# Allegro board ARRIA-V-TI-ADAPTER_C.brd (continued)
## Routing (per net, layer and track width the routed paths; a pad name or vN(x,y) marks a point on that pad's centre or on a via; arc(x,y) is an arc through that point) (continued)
DA2N: length 162.7
  TOP w0.114: J2.153 222.25,36.96 222.17,37.04 214.13,37.04 214,36.92 214,17.91 213.7,17.6 124.84,17.6 124.55,17.89 124.55,21.06 124.42,21.18 124.1,21.18 123.98,21.06 123.98,17.89 123.69,17.6 122.68,17.6 122.38,17.91 122.38,22.63 122.26,22.75 121.92,22.75 121.8,22.63 121.8,19.69 121.5,19.38 120.93,19.38 120.62,19.69 120.62,22.63 120.51,22.75 120.17,22.75 120.05,22.63 120.05,19.69 119.75,19.38 119.18,19.38 118.87,19.69 118.87,22.43 118.53,22.77 105.93,22.77 v1(105.42,22.26)
  BOTTOM w0.114: v1(105.42,22.26) J3.H10
DA2P: length 162.7
  TOP w0.114: v1(105.42,23.53) 105.88,23.08 118.66,23.08 119.18,22.56 119.18,19.81 119.3,19.68 119.62,19.68 119.75,19.81 119.75,22.76 120.04,23.05 120.64,23.05 120.93,22.76 120.93,19.81 121.05,19.68 121.37,19.68 121.5,19.81 121.5,22.76 121.79,23.05 122.39,23.05 122.68,22.76 122.68,18.03 122.81,17.91 123.56,17.91 123.67,18.02 123.67,21.18 123.98,21.49 124.55,21.49 124.85,21.18 124.85,18.02 124.97,17.91 213.57,17.91 213.7,18.03 213.7,37.04 214.01,37.35 222.14,37.35 222.25,37.46 J2.151
  BOTTOM w0.114: v1(105.42,23.53) J3.H11
DA3N: length 161.2
  TOP w0.114: v1(99.07,27.34) 99.11,27.38 99.11,27.71 99.24,27.84 99.44,27.84 99.57,27.71 99.57,25.58 99.85,25.3 103.15,25.3 103.38,25.06 103.38,24.48 103.39,24.48 103.39,24.32 103.71,24 126.11,24 126.24,23.88 126.24,20.04 126.54,19.74 127.46,19.74 127.76,20.04 127.76,23.88 127.89,24 128.4,24 128.52,23.88 128.52,19.43 128.83,19.13 211.53,19.13 211.84,19.43 211.84,38.43 211.96,38.56 222.4,38.56 222.49,38.46 J2.147
  BOTTOM w0.114: v1(99.07,27.34) J3.C14
DA3P: length 161.2
  TOP w0.114: v1(99.07,28.61) 99.09,28.6 99.09,28.24 99.19,28.14 99.57,28.14 99.87,27.84 99.87,25.7 99.97,25.6 103.28,25.6 103.69,25.19 103.69,24.61 103.7,24.6 103.7,24.45 103.83,24.31 126.24,24.31 126.54,24 126.54,20.17 126.67,20.04 127.33,20.04 127.46,20.17 127.46,24 127.76,24.31 128.52,24.31 128.83,24 128.83,19.56 128.96,19.43 211.4,19.43 211.53,19.56 211.53,38.56 211.84,38.87 222.4,38.87 222.49,38.96 J2.145
  BOTTOM w0.114: v1(99.07,28.61) J3.C15
DA4N: length 162.1
  TOP w0.114: J2.141 222.49,39.96 222.4,40.06 210.18,40.06 209.99,39.88 209.99,21.4 209.37,20.78 138.16,20.78 137.87,21.07 137.87,21.54 137.74,21.67 137.42,21.67 137.29,21.54 137.29,21.07 137,20.78 135.86,20.78 135.57,21.07 135.57,25.15 135.44,25.27 134.67,25.27 134.54,25.15 134.54,21.08 134.24,20.78 133.27,20.78 132.97,21.08 132.97,25.15 132.84,25.27 132,25.27 131.88,25.15 131.88,21.21 131.57,20.9 130.73,20.9 130.43,21.21 130.43,25.16 130.3,25.29 104.28,25.29 104.15,25.16 v1(104.15,24.8)
  BOTTOM w0.114: v1(104.15,24.8) J3.G12
DA4P: length 162.1
  TOP w0.114: v1(104.15,26.07) 104.15,25.72 104.28,25.59 130.43,25.59 130.73,25.29 130.73,21.34 130.86,21.21 131.44,21.21 131.57,21.34 131.57,25.27 131.88,25.58 132.97,25.58 133.27,25.27 133.27,21.21 133.4,21.08 134.11,21.08 134.24,21.21 134.24,25.27 134.54,25.58 135.57,25.58 135.88,25.27 135.88,21.2 135.99,21.08 136.87,21.08 136.99,21.2 136.99,21.67 137.29,21.97 137.86,21.97 138.17,21.67 138.17,21.2 138.28,21.08 209.25,21.08 209.69,21.53 209.69,40.01 210.05,40.37 222.4,40.37 222.49,40.46 J2.139
  BOTTOM w0.114: v1(104.15,26.07) J3.G13
DA5N: length 160.7
  TOP w0.114: J2.135 222.49,41.47 222.4,41.56 208.82,41.56 208.53,41.28 208.53,22.61 208.23,22.3 142.32,22.3 142.03,22.59 142.03,26.33 141.9,26.45 141.4,26.45 141.27,26.33 141.27,23.51 140.97,23.2 140.26,23.2 139.95,23.51 139.95,26.29 139.83,26.42 138.99,26.42 138.86,26.29 138.86,23.5 138.56,23.19 137.47,23.19 137.16,23.5 137.16,26.43 137.03,26.56 102.41,26.56 102.11,26.86 102.11,27.66 101.94,27.83 100.47,27.83 100.34,27.7 v1(100.34,27.34)
  BOTTOM w0.114: v1(100.34,27.34) J3.D14
DA5P: length 160.7
  TOP w0.114: J2.133 222.49,41.97 222.4,41.87 208.7,41.87 208.23,41.4 208.23,22.73 208.1,22.61 142.45,22.61 142.33,22.72 142.33,26.45 142.03,26.76 141.28,26.76 140.97,26.45 140.97,23.63 140.84,23.51 140.39,23.51 140.26,23.63 140.26,26.42 139.95,26.72 138.86,26.72 138.56,26.42 138.56,23.62 138.43,23.5 137.59,23.5 137.46,23.62 137.46,26.56 137.16,26.86 102.54,26.86 102.41,26.99 102.41,27.79 102.07,28.13 100.47,28.13 100.34,28.26 v1(100.34,28.61)
  BOTTOM w0.114: v1(100.34,28.61) J3.D15
DA6N: length 162.5
  TOP w0.114: v1(104.15,28.61) 104.63,29.1 105.63,29.1 105.89,28.83 105.89,28.13 106.2,27.83 144.14,27.83 144.27,27.7 144.27,24.64 144.58,24.33 145.41,24.33 145.72,24.64 145.72,27.7 145.85,27.83 146.43,27.83 146.56,27.7 146.56,24.64 146.86,24.33 147.7,24.33 148.01,24.64 148.01,27.69 148.13,27.81 148.71,27.81 148.84,27.69 148.84,24.64 149.15,24.33 149.94,24.33 150.24,24.64 150.24,27.58 150.37,27.71 150.83,27.71 150.95,27.58 150.95,24.64 151.26,24.33 205.99,24.33 206.3,24.64 206.3,42.67 206.69,43.06 222.4,43.06 222.49,42.97 J2.129
  BOTTOM w0.114: v1(104.15,28.61) J3.G15
DA6P: length 162.5
  TOP w0.114: v1(104.15,29.88) 104.63,29.4 105.75,29.4 106.2,28.96 106.2,28.26 106.32,28.13 144.27,28.13 144.58,27.83 144.58,24.77 144.7,24.64 145.29,24.64 145.41,24.77 145.41,27.83 145.72,28.13 146.56,28.13 146.86,27.83 146.86,24.77 146.99,24.64 147.57,24.64 147.7,24.77 147.7,27.81 148.01,28.12 148.84,28.12 149.15,27.81 149.15,24.77 149.27,24.64 149.81,24.64 149.94,24.77 149.94,27.71 150.24,28.02 150.95,28.02 151.26,27.71 151.26,24.77 151.38,24.64 205.87,24.64 205.99,24.77 205.99,42.8 206.56,43.37 222.4,43.37 222.49,43.47 J2.127
  BOTTOM w0.114: v1(104.15,29.88) J3.G16
DA7N: length 129.9
  TOP w0.114: v1(106.69,28.61) 107.17,29.1 198.08,29.1 203.96,34.98 203.96,43.89 204.64,44.57 222.4,44.57 222.49,44.47 J2.123
  BOTTOM w0.114: v1(106.69,28.61) J3.J15
DA7P: length 129.9
  TOP w0.114: v1(106.69,29.88) 107.17,29.4 197.96,29.4 203.66,35.1 203.66,44.02 204.51,44.87 222.4,44.87 222.49,44.97 J2.121
  BOTTOM w0.114: v1(106.69,29.88) J3.J16
DA8N: length 161.3
  TOP w0.114: J2.111 222.49,52.46 222.4,52.56 219.46,52.56 219.33,52.43 219.33,47.37 219.02,47.07 218.25,47.07 217.94,47.37 217.94,52.44 217.83,52.56 217.49,52.56 217.37,52.44 217.37,47.37 217.07,47.07 216.33,47.07 216.03,47.37 216.03,49.24 215.9,49.37 215.44,49.37 215.32,49.24 215.32,46.91 215.01,46.61 197.23,46.61 196.72,46.1 196.72,31.37 195.72,30.37 102.41,30.37 102.11,30.67 102.11,31.47 101.94,31.64 100.82,31.64 v1(100.34,31.15)
  BOTTOM w0.114: v1(100.34,31.15) J3.D17
DA8P: length 161.3
  TOP w0.114: J2.109 222.49,52.96 222.4,52.86 219.33,52.86 219.02,52.56 219.02,47.5 218.9,47.37 218.38,47.37 218.25,47.5 218.25,52.57 217.96,52.86 217.36,52.86 217.07,52.57 217.07,47.5 216.94,47.37 216.46,47.37 216.33,47.5 216.33,49.37 216.03,49.68 215.32,49.68 215.01,49.37 215.01,47.04 214.88,46.91 197.1,46.91 196.42,46.23 196.42,31.5 195.59,30.67 102.54,30.67 102.41,30.8 102.41,31.6 102.07,31.94 100.82,31.94 v1(100.34,32.42)
  BOTTOM w0.114: v1(100.34,32.42) J3.D18
DA9N: length 160.9
  TOP w0.114: v1(104.15,32.42) 104.63,32.91 105.75,32.91 105.92,32.74 105.92,31.94 106.22,31.64 192.67,31.64 193.55,32.51 193.55,47.57 194.49,48.51 208.03,48.51 208.41,48.9 208.41,50.29 208.53,50.42 209.25,50.42 209.37,50.29 209.37,48.82 209.68,48.51 210.51,48.51 210.82,48.82 210.82,53.93 210.95,54.06 211.4,54.06 211.53,53.93 211.53,48.82 211.84,48.51 212.8,48.51 213.11,48.82 213.11,53.93 213.23,54.06 213.69,54.06 213.82,53.93 213.82,52.03 214.12,51.73 215.21,51.73 215.52,52.03 215.52,53.93 215.65,54.06 222.4,54.06 222.49,53.96 J2.105
  BOTTOM w0.114: v1(104.15,32.42) J3.G18
DA9P: length 160.9
  TOP w0.114: J2.103 222.49,54.46 222.4,54.36 215.52,54.36 215.21,54.06 215.21,52.16 215.09,52.03 214.25,52.03 214.12,52.16 214.12,54.06 213.82,54.36 213.11,54.36 212.8,54.06 212.8,48.95 212.67,48.82 211.96,48.82 211.84,48.95 211.84,54.06 211.53,54.36 210.82,54.36 210.52,54.06 210.52,48.95 210.39,48.82 209.8,48.82 209.68,48.95 209.68,50.42 209.37,50.72 208.41,50.72 208.1,50.42 208.1,49.02 207.9,48.82 194.36,48.82 193.24,47.7 193.24,32.64 192.55,31.94 106.35,31.94 106.22,32.07 106.22,32.87 105.88,33.21 104.63,33.21 v1(104.15,33.69)
  BOTTOM w0.114: v1(104.15,33.69) J3.G19
DA10N: length 160.9
  TOP w0.114: J2.99 222.49,55.46 222.4,55.56 209.36,55.56 209.3,55.5 209.3,52.71 208.99,52.4 208.23,52.4 207.92,52.71 207.92,55.37 207.79,55.5 206.76,55.5 206.63,55.37 206.63,51.05 206.32,50.75 205.16,50.75 204.85,51.05 204.85,55.43 204.72,55.56 204.09,55.56 203.96,55.43 203.96,51.05 203.66,50.75 202.44,50.75 202.13,51.05 202.13,54.1 202.01,54.23 201.29,54.23 201.17,54.1 201.17,51.31 200.53,50.67 191.26,50.67 190.88,50.29 190.88,34.04 189.75,32.91 107.17,32.91 v1(106.69,32.42)
  BOTTOM w0.114: v1(106.69,32.42) J3.J18
DA10P: length 160.9
  TOP w0.114: v1(106.69,33.69) 107.17,33.21 189.62,33.21 190.58,34.16 190.58,50.42 191.13,50.98 200.41,50.98 200.86,51.43 200.86,54.23 201.17,54.53 202.13,54.53 202.44,54.23 202.44,51.18 202.56,51.05 203.53,51.05 203.66,51.18 203.66,55.56 203.96,55.87 204.85,55.87 205.16,55.56 205.16,51.18 205.28,51.05 206.2,51.05 206.32,51.18 206.32,55.5 206.63,55.8 207.92,55.8 208.23,55.5 208.23,52.83 208.35,52.7 208.86,52.7 208.99,52.83 208.99,55.63 209.23,55.87 222.4,55.87 222.49,55.96 J2.97
  BOTTOM w0.114: v1(106.69,33.69) J3.J19
DA11N: length 155.8
  TOP w0.114: J2.93 222.49,56.96 222.4,57.06 199.52,57.06 199.39,56.94 199.39,52.71 199.08,52.4 198.25,52.4 197.94,52.71 197.94,56.9 197.82,57.02 197.23,57.02 197.1,56.9 197.1,52.71 196.8,52.4 195.97,52.4 195.66,52.71 195.66,56.72 195.54,56.85 194.87,56.85 194.74,56.72 194.74,52.63 194.44,52.32 188.14,52.32 187.71,51.89 187.71,35.31 186.58,34.18 108.44,34.18 v1(107.96,33.69)
  BOTTOM w0.114: v1(107.96,33.69) J3.K19
DA11P: length 155.8
  TOP w0.114: J2.91 222.49,57.46 222.4,57.37 199.39,57.37 199.09,57.06 199.09,52.83 198.96,52.7 198.37,52.7 198.25,52.83 198.25,57.02 197.94,57.33 197.1,57.33 196.8,57.02 196.8,52.83 196.67,52.7 196.09,52.7 195.97,52.83 195.97,56.84 195.66,57.15 194.74,57.15 194.44,56.84 194.44,52.76 194.31,52.63 188.01,52.63 187.4,52.02 187.4,35.43 186.45,34.48 108.44,34.48 v1(107.96,34.96)
  BOTTOM w0.114: v1(107.96,34.96) J3.K20
DA12N: length 160.8
  TOP w0.114: v1(101.61,32.42) 102.09,32.91 103.19,32.91 103.68,33.4 103.68,35.18 103.93,35.43 183.89,35.43 184.91,36.45 184.91,53.8 185.04,53.92 188.09,53.92 188.39,54.23 188.39,58.42 188.52,58.55 189.1,58.55 189.23,58.42 189.23,55.13 189.54,54.83 190.25,54.83 190.55,55.13 190.55,58.42 190.68,58.55 191.21,58.55 191.34,58.42 191.34,55.5 191.64,55.19 192.61,55.19 192.91,55.5 192.91,58.44 193.04,58.56 222.4,58.56 222.49,58.47 J2.87
  BOTTOM w0.114: v1(101.61,32.42) J3.E18
DA12P: length 160.8
  TOP w0.114: J2.85 222.49,58.97 222.4,58.87 192.91,58.87 192.61,58.56 192.61,55.63 192.48,55.5 191.77,55.5 191.64,55.63 191.64,58.55 191.34,58.85 190.55,58.85 190.25,58.55 190.25,55.26 190.12,55.13 189.66,55.13 189.53,55.26 189.53,58.55 189.23,58.85 188.39,58.85 188.09,58.55 188.09,54.36 187.96,54.23 184.91,54.23 184.61,53.92 184.61,36.58 183.76,35.73 103.8,35.73 103.38,35.31 103.38,33.53 103.06,33.21 102.09,33.21 v1(101.61,33.69)
  BOTTOM w0.114: v1(101.61,33.69) J3.E19
DA13N: length 159.4
  TOP w0.114: J2.81 222.49,59.97 222.4,60.06 179.84,60.06 179.72,59.94 179.72,59.05 179.84,58.93 185.04,58.93 185.34,58.62 185.34,57.4 185.04,57.1 182.17,57.1 182.04,56.97 182.04,37.04 181.74,36.74 102.6,36.74 102.42,36.55 102.42,35.9 101.97,35.45 100.82,35.45 v1(100.34,34.96)
  BOTTOM w0.114: v1(100.34,34.96) J3.D20
DA13P: length 159.4
  TOP w0.114: J2.79 222.49,60.47 222.4,60.37 179.72,60.37 179.41,60.06 179.41,58.93 179.72,58.62 184.91,58.62 185.04,58.5 185.04,57.53 184.91,57.4 182.04,57.4 181.74,57.1 181.74,37.17 181.61,37.04 102.48,37.04 102.11,36.68 102.11,36.02 101.84,35.75 100.82,35.75 v1(100.34,36.23)
  BOTTOM w0.114: v1(100.34,36.23) J3.D21
DA14N: length 161
  TOP w0.114: v1(105.42,37.5) 105.9,37.99 174.51,37.99 175.51,38.99 175.51,50.35 175.63,50.47 178.54,50.47 178.84,50.77 178.84,51.34 178.54,51.65 175.63,51.65 175.51,51.76 175.51,52.11 175.63,52.22 178.54,52.22 178.84,52.53 178.84,53.1 178.54,53.4 175.63,53.4 175.51,53.52 175.51,53.86 175.63,53.97 178.55,53.97 178.85,54.28 178.85,54.85 178.55,55.15 175.63,55.15 175.51,55.27 175.51,61.44 175.64,61.57 222.4,61.57 222.49,61.47 J2.75
  BOTTOM w0.114: v1(105.42,37.5) J3.H22
DA14P: length 161
  TOP w0.114: J2.73 222.49,61.97 222.4,61.87 175.51,61.87 175.21,61.57 175.21,55.14 175.5,54.85 178.42,54.85 178.55,54.72 178.55,54.41 178.42,54.28 175.5,54.28 175.21,53.99 175.21,53.39 175.5,53.1 178.41,53.1 178.54,52.97 178.54,52.65 178.41,52.53 175.5,52.53 175.21,52.23 175.21,51.64 175.5,51.34 178.41,51.34 178.54,51.22 178.54,50.9 178.41,50.77 175.5,50.77 175.21,50.48 175.21,39.12 174.38,38.29 105.9,38.29 v1(105.42,38.77)
  BOTTOM w0.114: v1(105.42,38.77) J3.H23
DA15N: length 158.6
  TOP w0.114: v1(99.07,37.5) 99.56,37.99 104.53,37.99 104.92,38.37 104.92,39.14 105.05,39.27 172.47,39.27 172.97,39.78 172.97,62.94 173.1,63.07 207.27,63.07 207.56,63.36 207.56,65.27 207.69,65.39 208.01,65.39 208.14,65.27 208.14,63.36 208.43,63.07 209.02,63.07 209.32,63.36 209.32,65.27 209.44,65.39 209.76,65.39 209.89,65.27 209.89,63.36 210.18,63.07 222.4,63.07 222.49,62.97 J2.69
  BOTTOM w0.114: v1(99.07,37.5) J3.C22
DA15P: length 158.6
  TOP w0.114: J2.67 222.49,63.47 222.4,63.37 210.31,63.37 210.19,63.49 210.19,65.39 209.89,65.7 209.32,65.7 209.01,65.39 209.01,63.49 208.9,63.37 208.55,63.37 208.44,63.49 208.44,65.39 208.14,65.7 207.56,65.7 207.26,65.39 207.26,63.49 207.15,63.37 172.97,63.37 172.67,63.07 172.67,39.9 172.34,39.57 104.92,39.57 104.62,39.27 104.62,38.5 104.41,38.29 99.56,38.29 v1(99.07,38.77)
  BOTTOM w0.114: v1(99.07,38.77) J3.C23
DAC_RST: length 198
  LAYER3 w0.124: v1(210.69,73.66) 210.69,76.58 176.05,111.23 61.82,111.23 52.07,101.47 52.07,92.33 v1(50.91,91.17)
  BOTTOM w0.165: v1(210.69,73.66) R5.1 ; J4.139 v1(50.91,91.17)
DATACLKN: length 141.8
  TOP w0.114: J2.115 222.49,51.46 222.4,51.36 221.47,51.36 v1(221.17,51.66)
  BOTTOM w0.114: J3.J10 106.69,22.26 107.71,22.26 108.28,21.69 170.82,21.69 170.94,21.81 170.94,24.13 171.24,24.43 171.81,24.43 172.12,24.13 172.12,21.81 172.23,21.69 172.58,21.69 172.69,21.81 172.69,24.61 173,24.92 173.57,24.92 173.87,24.61 173.87,21.81 173.99,21.69 174.57,21.69 202.84,49.96 218.31,49.96 219.79,51.44 220.94,51.44 v1(221.17,51.66)
DATACLKP: length 141.8
  TOP w0.114: J2.117 222.49,50.96 222.4,51.06 221.47,51.06 v1(221.17,50.76)
  BOTTOM w0.114: J3.J9 106.69,20.99 107.79,20.99 108.18,21.39 170.95,21.39 171.24,21.68 171.24,24 171.37,24.13 171.69,24.13 171.81,24 171.81,21.68 172.11,21.39 172.7,21.39 172.99,21.68 172.99,24.49 173.12,24.61 173.44,24.61 173.57,24.49 173.57,21.68 173.86,21.39 174.7,21.39 202.97,49.66 218.44,49.66 219.91,51.13 220.8,51.13 v1(221.17,50.76)
DB0N: length 157.5
  TOP w0.114: v1(232.16,33.76) 231.86,34.06 230.99,34.06 230.9,33.96 J2.166
  LAYER3 w0.112: v1(102.88,18.45) 103.36,18.94 210.31,18.94 210.62,19.24 210.62,23.56 210.74,23.69 211.44,23.69 211.57,23.56 211.57,19.23 211.86,18.94 213.11,18.94 213.41,19.24 213.41,33.91 213.56,34.06 225.58,34.06 225.98,33.66 227.2,33.66 227.61,34.06 231.86,34.06 v1(232.16,33.76)
  BOTTOM w0.114: v1(102.88,18.45) J3.F7
DB0P: length 157.5
  TOP w0.114: J2.164 230.9,34.46 230.99,34.36 231.86,34.36 v1(232.16,34.66)
  LAYER3 w0.112: v1(102.88,19.72) 103.36,19.24 210.19,19.24 210.31,19.37 210.31,23.68 210.62,23.99 211.57,23.99 211.87,23.68 211.87,19.35 211.98,19.24 212.98,19.24 213.11,19.37 213.11,34.04 213.43,34.36 225.71,34.36 226.11,33.96 227.08,33.96 227.48,34.36 231.86,34.36 v1(232.16,34.66)
  BOTTOM w0.114: v1(102.88,19.72) J3.F8
DB1N: length 158.6
  TOP w0.114: v1(227.5,35.26) 227.8,35.56 228.13,35.56 228.22,35.46 J2.160
  LAYER3 w0.112: v1(227.5,35.26) 227.2,35.56 208.46,35.56 208.33,35.43 208.33,21.78 208.03,21.48 206.78,21.48 206.49,21.77 206.49,29.3 206.36,29.43 205.41,29.43 205.28,29.3 205.28,21.78 204.98,21.48 102.09,21.48 v1(101.61,20.99)
  BOTTOM w0.114: v1(101.61,20.99) J3.E9
DB1P: length 158.6
  TOP w0.114: v1(227.5,36.16) 227.8,35.86 228.13,35.86 228.22,35.96 J2.158
  LAYER3 w0.112: v1(101.61,22.26) 102.09,21.78 204.85,21.78 204.98,21.91 204.98,29.43 205.28,29.73 206.49,29.73 206.8,29.43 206.8,21.89 206.91,21.78 207.9,21.78 208.03,21.91 208.03,35.56 208.33,35.86 227.2,35.86 v1(227.5,36.16)
  BOTTOM w0.114: v1(101.61,22.26) J3.E10
DB2N: length 160.5
  TOP w0.114: v1(232.16,36.76) 231.86,37.06 230.99,37.06 230.9,36.96 J2.154
  LAYER3 w0.112: v1(101.61,24.8) 102.09,25.29 104.5,25.29 104.62,25.16 104.62,24.33 104.95,24 200.28,24 200.66,24.38 200.66,30.24 200.79,30.37 201.5,30.37 201.63,30.24 201.63,24.38 201.93,24.08 203.07,24.08 203.38,24.38 203.38,36.7 203.73,37.06 225.93,37.06 226.24,37.36 227.28,37.36 227.58,37.06 231.86,37.06 v1(232.16,36.76)
  BOTTOM w0.114: v1(101.61,24.8) J3.E12
DB2P: length 160.5
  TOP w0.114: v1(232.16,37.66) 231.86,37.36 230.99,37.36 230.9,37.46 J2.152
  LAYER3 w0.112: v1(232.16,37.66) 231.86,37.36 227.71,37.36 227.41,37.67 226.11,37.67 225.81,37.36 203.61,37.36 203.07,36.83 203.07,24.51 202.95,24.38 202.06,24.38 201.93,24.51 201.93,30.37 201.62,30.67 200.66,30.67 200.36,30.37 200.36,24.51 200.15,24.31 105.08,24.31 104.93,24.46 104.93,25.29 104.62,25.59 102.09,25.59 v1(101.61,26.07)
  BOTTOM w0.114: v1(101.61,26.07) J3.E13
DB3N: length 153.9
  TOP w0.114: v1(227.5,38.26) 227.8,38.56 228.13,38.56 228.22,38.46 J2.148
  LAYER3 w0.112: v1(227.5,38.26) 227.2,38.56 199.01,38.56 198.68,38.23 198.68,25.65 198.37,25.35 197.03,25.35 196.72,25.65 196.72,33.86 196.6,33.99 195.63,33.99 195.5,33.86 195.5,25.59 195.2,25.29 107.17,25.29 v1(106.69,24.8)
  BOTTOM w0.114: v1(106.69,24.8) J3.J12
DB3P: length 153.9
  TOP w0.114: v1(227.5,39.17) 227.8,38.87 228.13,38.87 228.22,38.96 J2.146
  LAYER3 w0.112: v1(227.5,39.17) 227.2,38.87 198.89,38.87 198.37,38.35 198.37,25.78 198.25,25.65 197.15,25.65 197.03,25.78 197.03,33.98 196.72,34.29 195.5,34.29 195.2,33.98 195.2,25.72 195.07,25.59 107.17,25.59 v1(106.69,26.07)
  BOTTOM w0.114: v1(106.69,26.07) J3.J13
DB4N: length 161.2
  TOP w0.114: v1(232.16,39.76) 231.86,40.06 230.99,40.06 230.9,39.96 J2.142
  LAYER3 w0.112: v1(232.16,39.76) 231.86,40.06 192.89,40.06 192.71,39.88 192.71,26.92 192.4,26.62 191.01,26.62 190.7,26.92 190.7,34.1 190.58,34.23 189.84,34.23 189.72,34.1 189.72,26.85 189.43,26.56 103.36,26.56 v1(102.88,26.07)
  BOTTOM w0.114: v1(102.88,26.07) J3.F13
DB4P: length 161.2
  TOP w0.114: J2.140 230.9,40.46 230.99,40.37 231.86,40.37 v1(232.16,40.67)
  LAYER3 w0.112: v1(232.16,40.67) 231.86,40.37 192.77,40.37 192.41,40.01 192.41,27.05 192.28,26.92 191.13,26.92 191.01,27.05 191.01,34.23 190.7,34.53 189.72,34.53 189.41,34.23 189.41,26.97 189.3,26.86 103.36,26.86 v1(102.88,27.34)
  BOTTOM w0.114: v1(102.88,27.34) J3.F14
DB5N: length 158.5
  TOP w0.114: v1(227.5,41.26) 227.8,41.56 228.13,41.56 228.22,41.47 J2.136
  LAYER3 w0.112: v1(227.5,41.26) 227.2,41.56 186.9,41.56 186.74,41.4 186.74,29.34 186.44,29.03 184.66,29.03 184.35,29.34 184.35,37.64 184.23,37.77 183.29,37.77 183.16,37.64 183.16,29.39 182.87,29.1 102.09,29.1 v1(101.61,28.61)
  BOTTOM w0.114: v1(101.61,28.61) J3.E15
DB5P: length 158.5
  TOP w0.114: J2.134 228.22,41.97 228.13,41.87 227.8,41.87 v1(227.5,42.17)
  LAYER3 w0.112: v1(227.5,42.17) 227.2,41.87 186.77,41.87 186.44,41.53 186.44,29.46 186.31,29.34 184.78,29.34 184.66,29.46 184.66,37.77 184.35,38.07 183.17,38.07 182.86,37.77 182.86,29.51 182.75,29.4 102.09,29.4 v1(101.61,29.88)
  BOTTOM w0.114: v1(101.61,29.88) J3.E16
DB6N: length 161
  TOP w0.114: v1(232.16,42.76) 231.86,43.06 230.99,43.06 230.9,42.97 J2.130
  LAYER3 w0.112: v1(232.16,42.76) 231.86,43.06 180.53,43.06 180.39,42.93 180.39,30.73 180.09,30.43 178.94,30.43 178.64,30.73 178.64,38.2 178.51,38.33 177.34,38.33 177.22,38.2 177.22,30.67 176.91,30.37 103.36,30.37 v1(102.88,29.88)
  BOTTOM w0.114: v1(102.88,29.88) J3.F16
DB6P: length 161
  TOP w0.114: J2.128 230.9,43.47 230.99,43.37 231.86,43.37 v1(232.16,43.67)
  LAYER3 w0.112: v1(102.88,31.15) 103.36,30.67 176.78,30.67 176.91,30.8 176.91,38.33 177.22,38.63 178.64,38.63 178.94,38.33 178.94,30.86 179.07,30.73 179.96,30.73 180.09,30.86 180.09,43.05 180.4,43.37 231.86,43.37 v1(232.16,43.67)
  BOTTOM w0.114: v1(102.88,31.15) J3.F17
DB7N: length 160.9
  TOP w0.114: v1(227.5,44.27) 227.8,44.57 228.13,44.57 228.22,44.47 J2.124
  LAYER3 w0.112: v1(227.5,44.27) 227.2,44.57 175.04,44.57 174.92,44.45 174.92,36.96 174.62,36.65 173.66,36.65 173.35,36.96 173.35,44.58 173.23,44.7 172.26,44.7 172.14,44.58 172.14,37.02 171.83,36.72 170.45,36.72 170.16,37.01 170.16,43.54 170.03,43.66 169.34,43.66 169.21,43.54 169.21,37.02 168.91,36.72 107.17,36.72 v1(106.69,36.23)
  BOTTOM w0.114: v1(106.69,36.23) J3.J21
DB7P: length 160.9
  TOP w0.114: v1(227.5,45.17) 227.8,44.87 228.13,44.87 228.22,44.97 J2.122
  LAYER3 w0.112: v1(227.5,45.17) 227.2,44.87 174.91,44.87 174.62,44.58 174.62,37.08 174.49,36.96 173.79,36.96 173.66,37.08 173.66,44.7 173.35,45.01 172.14,45.01 171.83,44.7 171.83,37.15 171.7,37.02 170.57,37.02 170.46,37.13 170.46,43.66 170.16,43.97 169.22,43.97 168.91,43.66 168.91,37.15 168.78,37.02 107.17,37.02 v1(106.69,37.5)
  BOTTOM w0.114: v1(106.69,37.5) J3.J22
DB8N: length 154.8
  TOP w0.114: J2.112 230.9,52.46 230.99,52.56 231.86,52.56 v1(232.16,52.26)
  LAYER3 w0.112: v1(107.96,37.5) 108.44,37.99 165.61,37.99 165.91,38.29 165.91,51.82 166.04,51.94 166.88,51.94 167,51.82 167,45.97 167.31,45.67 168.91,45.67 169.21,45.97 169.21,52.32 169.47,52.58 225.91,52.58 226.26,52.93 226.96,52.93 227.33,52.56 231.86,52.56 v1(232.16,52.26)
  BOTTOM w0.114: v1(107.96,37.5) J3.K22
DB8P: length 154.8
  TOP w0.114: v1(232.16,53.16) 231.86,52.86 230.99,52.86 230.9,52.96 J2.110
  LAYER3 w0.112: v1(107.96,38.77) 108.44,38.29 165.48,38.29 165.61,38.42 165.61,51.94 165.91,52.25 167,52.25 167.31,51.94 167.31,46.1 167.44,45.97 168.78,45.97 168.91,46.1 168.91,52.45 169.34,52.88 225.78,52.88 226.14,53.24 227.08,53.24 227.46,52.86 231.86,52.86 v1(232.16,53.16)
  BOTTOM w0.114: v1(107.96,38.77) J3.K23
DB9N: length 149.1
  TOP w0.114: v1(227.5,53.76) 227.8,54.06 228.13,54.06 228.22,53.96 J2.106
  LAYER3 w0.112: v1(104.15,40.04) 104.63,40.53 159.51,40.53 159.89,40.91 159.89,45.25 160.02,45.38 161.04,45.38 161.16,45.25 161.16,40.89 161.47,40.59 163.19,40.59 163.5,40.89 163.5,53.86 163.7,54.06 227.2,54.06 v1(227.5,53.76)
  BOTTOM w0.114: v1(104.15,40.04) J3.G24
DB9P: length 149.1
  TOP w0.114: J2.104 228.22,54.46 228.13,54.36 227.8,54.36 v1(227.5,54.66)
  LAYER3 w0.112: v1(104.15,41.31) 104.63,40.83 159.39,40.83 159.59,41.03 159.59,45.38 159.89,45.68 161.16,45.68 161.47,45.38 161.47,41.02 161.59,40.89 163.07,40.89 163.19,41.02 163.19,53.98 163.58,54.36 227.2,54.36 v1(227.5,54.66)
  BOTTOM w0.114: v1(104.15,41.31) J3.G25
DB10N: length 157.5
  TOP w0.114: J2.100 230.9,55.46 230.99,55.56 231.86,55.56 v1(232.16,55.26)
  LAYER3 w0.112: v1(232.16,55.26) 231.86,55.56 158.48,55.56 157.91,54.99 157.91,48.01 157.61,47.7 156.52,47.7 156.21,48.01 156.21,54.61 156.08,54.74 155.24,54.74 155.12,54.61 155.12,42.1 154.81,41.8 105.9,41.8 v1(105.42,41.31)
  BOTTOM w0.114: v1(105.42,41.31) J3.H25
DB10P: length 157.5
  TOP w0.114: J2.98 230.9,55.96 230.99,55.87 231.86,55.87 v1(232.16,56.17)
  LAYER3 w0.112: v1(232.16,56.17) 231.86,55.87 158.36,55.87 157.61,55.12 157.61,48.13 157.48,48.01 156.64,48.01 156.51,48.13 156.51,54.74 156.21,55.04 155.12,55.04 154.81,54.74 154.81,42.23 154.69,42.1 105.9,42.1 v1(105.42,42.58)
  BOTTOM w0.114: v1(105.42,42.58) J3.H26
DB11N: length 161.1
  TOP w0.114: J2.94 228.22,56.96 228.13,57.06 227.8,57.06 v1(227.5,56.76)
  LAYER3 w0.112: v1(227.5,56.76) 227.2,57.06 152.74,57.06 152.45,56.77 152.45,43.43 152.15,43.13 151,43.13 150.7,43.43 150.7,48.59 150.57,48.72 149.66,48.72 149.53,48.59 149.53,43.43 149.22,43.13 147.96,43.13 147.65,43.43 147.65,45.72 147.52,45.85 146.49,45.85 146.37,45.72 146.37,43.36 146.08,43.07 99.55,43.07 v1(99.07,42.58)
  BOTTOM w0.114: v1(99.07,42.58) J3.C26
DB11P: length 161.1
  TOP w0.114: J2.92 228.22,57.46 228.13,57.37 227.8,57.37 v1(227.5,57.67)
  LAYER3 w0.112: v1(227.5,57.67) 227.2,57.37 152.62,57.37 152.15,56.9 152.15,43.56 152.02,43.43 151.13,43.43 151,43.56 151,48.72 150.7,49.02 149.53,49.02 149.22,48.72 149.22,43.56 149.1,43.43 148.08,43.43 147.95,43.56 147.95,45.85 147.65,46.15 146.37,46.15 146.06,45.85 146.06,43.48 145.95,43.37 99.55,43.37 v1(99.07,43.85)
  BOTTOM w0.114: v1(99.07,43.85) J3.C27
DB12N: length 151.8
  TOP w0.114: J2.88 230.9,58.47 230.99,58.56 231.86,58.56 v1(232.16,58.26)
  LAYER3 w0.112: v1(232.16,58.26) 231.86,58.56 150.18,58.56 149.99,58.37 149.99,52.12 149.68,51.82 148.77,51.82 148.46,52.12 148.46,58.04 148.34,58.17 147.75,58.17 147.62,58.04 147.62,49.72 147.32,49.42 105.9,49.42 v1(105.42,48.93)
  BOTTOM w0.114: v1(105.42,48.93) J3.H31
DB12P: length 151.8
  TOP w0.114: J2.86 230.9,58.97 230.99,58.87 231.86,58.87 v1(232.16,59.17)
  LAYER3 w0.112: v1(232.16,59.17) 231.86,58.87 150.05,58.87 149.68,58.5 149.68,52.25 149.56,52.12 148.89,52.12 148.77,52.25 148.77,58.17 148.46,58.47 147.63,58.47 147.32,58.17 147.32,49.85 147.19,49.72 105.9,49.72 v1(105.42,50.2)
  BOTTOM w0.114: v1(105.42,50.2) J3.H32
DB13N: length 145.7
  TOP w0.114: v1(227.5,59.76) 227.8,60.06 228.13,60.06 228.22,59.97 J2.82
  LAYER3 w0.112: v1(227.5,59.76) 227.2,60.06 145.59,60.06 145.38,59.86 145.38,53.3 145.07,53 144.2,53 143.89,53.3 143.89,59.94 143.76,60.07 142.93,60.07 142.8,59.94 142.8,53.53 142.49,53.23 105.9,53.23 v1(105.42,52.74)
  BOTTOM w0.114: v1(105.42,52.74) J3.H34
DB13P: length 145.7
  TOP w0.114: J2.80 228.22,60.47 228.13,60.37 227.8,60.37 v1(227.5,60.67)
  LAYER3 w0.112: v1(105.42,54.01) 105.9,53.53 142.37,53.53 142.49,53.66 142.49,60.07 142.8,60.38 143.89,60.38 144.2,60.07 144.2,53.43 144.32,53.3 144.95,53.3 145.07,53.43 145.07,59.98 145.46,60.37 227.2,60.37 v1(227.5,60.67)
  BOTTOM w0.114: v1(105.42,54.01) J3.H35
DB14N: length 134.4
  TOP w0.114: v1(232.16,61.27) 231.86,61.57 230.99,61.57 230.9,61.47 J2.76
  LAYER3 w0.112: v1(232.16,61.27) 231.86,61.57 141.99,61.57 136.19,55.77 104.63,55.77 v1(104.15,55.28)
  BOTTOM w0.114: v1(104.15,55.28) J3.G36
DB14P: length 134.4
  TOP w0.114: J2.74 230.9,61.97 230.99,61.87 231.86,61.87 v1(232.16,62.17)
  LAYER3 w0.112: v1(232.16,62.17) 231.86,61.87 141.86,61.87 136.06,56.07 104.63,56.07 v1(104.15,56.55)
  BOTTOM w0.114: v1(104.15,56.55) J3.G37
DB15N: length 139.2
  TOP w0.114: v1(227.5,62.77) 227.8,63.07 228.13,63.07 228.22,62.97 J2.70
  LAYER3 w0.112: v1(105.42,56.55) 105.9,57.04 134.24,57.04 134.54,57.34 134.54,66.99 134.67,67.12 212.42,67.12 212.55,66.99 212.55,63.37 212.85,63.07 227.2,63.07 v1(227.5,62.77)
  BOTTOM w0.114: v1(105.42,56.55) J3.H37
DB15P: length 139.2
  TOP w0.114: v1(227.5,63.67) 227.8,63.37 228.13,63.37 228.22,63.47 J2.68
  LAYER3 w0.112: v1(105.42,57.82) 105.9,57.34 134.11,57.34 134.24,57.47 134.24,67.12 134.54,67.42 212.55,67.42 212.85,67.12 212.85,63.5 212.98,63.37 227.2,63.37 v1(227.5,63.67)
  BOTTOM w0.114: v1(105.42,57.82) J3.H38
FPGA_CLKOUTN1: length 166.6
  TOP w0.114: v1(104.15,13.37) 104.63,12.89 221.23,12.89 221.36,13.02 221.36,27.43 221.97,28.04 224.1,28.04 225.63,29.57 225.63,47.27 226.21,47.85 230.84,47.85 231.65,48.67 231.65,50.83 231.42,51.06 230.99,51.06 230.9,50.96 J2.118
  BOTTOM w0.114: v1(104.15,13.37) J3.G3
FPGA_CLKOUTN2: length 175
  TOP w0.114: v1(221.3,76.77) 221.6,77.06 222.4,77.06 222.49,76.97 J2.33
  BOTTOM w0.114: v1(221.3,76.77) 221.6,77.07 222.55,77.07 222.66,76.95 222.66,76.54 222.79,76.42 222.99,76.42 223.12,76.54 223.12,76.95 223.23,77.07 225.1,77.07 225.35,77.32 227.76,77.32 228.7,76.38 228.7,49.07 227.46,47.83 212.55,47.83 179.52,14.8 107.44,14.8 107.33,14.91 J3.K5
FPGA_CLKOUTP1: length 167.6
  TOP w0.114: v1(104.15,12.1) 104.63,12.59 221.36,12.59 221.67,12.89 221.67,27.31 222.1,27.74 224.23,27.74 225.93,29.44 225.93,47.14 226.34,47.55 230.96,47.55 231.95,48.54 231.95,50.95 231.54,51.36 230.99,51.36 230.9,51.46 J2.116
  BOTTOM w0.114: v1(104.15,12.1) J3.G2
FPGA_CLKOUTP2: length 175
  TOP w0.114: v1(221.3,77.67) 221.6,77.37 222.4,77.37 222.49,77.47 J2.31
  BOTTOM w0.114: J3.K4 107.33,14.38 107.44,14.49 179.64,14.49 212.67,47.52 227.58,47.52 229.01,48.95 229.01,76.5 227.89,77.62 225.22,77.62 224.97,77.37 221.6,77.37 v1(221.3,77.67)
GPIO_0: length 205.7
  LAYER3 w0.124: v1(47.91,91.16) 47.58,91.49 47.58,93.81 48.26,94.49 48.26,102.49 59.03,113.26 177.02,113.26 212.72,77.55 v1(212.72,72.77)
  BOTTOM w0.165: J4.127 v1(47.91,91.16) ; v1(212.72,72.77) 213.11,72.39 R8.2
GPIO_1: length 205.9
  LAYER3 w0.124: v1(215.77,68.58) 212.22,72.14 212.22,77.34 176.81,112.75 59.79,112.75 48.89,101.85 48.89,92.41 v1(48.41,91.93)
  BOTTOM w0.165: J4.129 v1(48.41,91.93) ; v1(215.77,68.58) R12.2
GPIO_2: length 205.2
  LAYER3 w0.124: v1(49.41,91.05) 49.41,92.21 49.66,92.46 49.66,101.47 60.43,112.24 176.6,112.24 211.71,77.13 211.71,71.37 v1(215.77,67.31)
  BOTTOM w0.165: v1(215.77,67.31) R14.2 ; J4.133 v1(49.41,91.05)
ISTROBE_N: length 279.9
  TOP w0.114: v1(232.16,30.76) 231.86,31.06 230.99,31.06 230.9,30.96 J2.178
  LAYER6 w0.112: v1(105.42,26.07) 104.94,26.56 100.01,26.56 99.82,26.37 99.82,11.89 100.14,11.58 212.74,11.58 212.85,11.69 212.85,28.12 213.16,28.42 213.71,28.42 214.02,28.12 214.02,11.69 214.13,11.58 214.47,11.58 214.58,11.69 214.58,28.67 214.87,28.96 215.46,28.96 215.75,28.67 215.75,11.69 215.86,11.58 216.19,11.58 216.3,11.69 216.3,28.67 216.59,28.96 217.18,28.96 217.47,28.67 217.47,11.69 217.58,11.58 218.19,11.58 218.39,11.78 218.39,28.65 218.69,28.96 219.66,28.96 219.77,29.07 219.77,29.21 219.9,29.34 220.2,29.34 220.33,29.21 220.33,29.07 220.44,28.96 220.78,28.96 220.89,29.07 220.89,29.21 221.02,29.34 221.32,29.34 221.45,29.21 221.45,29.07 221.56,28.96 221.89,28.96 222.01,29.07 222.01,29.21 222.13,29.34 222.44,29.34 222.57,29.21 222.57,29.07 222.68,28.96 223.01,28.96 223.12,29.07 223.12,29.25 223.25,29.38 223.56,29.38 223.68,29.25 223.68,29.07 223.79,28.96 224.99,28.96 226.06,30.02 232.53,30.02 232.74,30.23 232.74,30.94 232.63,31.06 232.46,31.06 v1(232.16,30.76)
  BOTTOM w0.114: v1(105.42,26.07) J3.H13
ISTROBE_P: length 280
  TOP w0.114: J2.176 230.9,31.46 230.99,31.36 231.86,31.36 v1(232.16,31.66)
  LAYER6 w0.112: v1(105.42,27.34) 104.94,26.86 99.89,26.86 99.52,26.49 99.52,11.77 100.01,11.27 212.86,11.27 213.16,11.56 213.16,27.99 213.28,28.12 213.59,28.12 213.71,27.99 213.71,11.56 214,11.27 214.59,11.27 214.88,11.56 214.88,28.54 214.99,28.65 215.33,28.65 215.44,28.54 215.44,11.56 215.73,11.27 216.32,11.27 216.61,11.56 216.61,28.54 216.72,28.65 217.06,28.65 217.17,28.54 217.17,11.56 217.46,11.27 218.31,11.27 218.69,11.65 218.69,28.52 218.82,28.65 225.12,28.65 226.18,29.72 232.66,29.72 233.05,30.1 233.05,31.07 232.75,31.36 232.46,31.36 v1(232.16,31.66)
  BOTTOM w0.114: v1(105.42,27.34) J3.H14
OVR_AN: length 331.4
  LAYER3 w0.112: v1(207.84,144.95) 208.14,144.65 208.14,143.14 208.91,142.37 210.13,142.37 210.39,142.11 210.39,141.95 210.29,141.84 210.29,141.66 210.5,141.45 210.68,141.45 210.79,141.56 210.95,141.56 211.2,141.3 211.2,140.07 211.09,139.96 210.96,139.96 210.83,139.83 210.83,139.53 210.96,139.4 211.09,139.4 211.2,139.29 211.2,120.27 210.57,119.63 49.62,119.63 49.33,119.34 49.33,118.4 49.22,118.29 48.88,118.29 48.77,118.4 48.77,119.34 48.48,119.63 46.35,119.63 45.6,118.88 45.6,118.47 48.91,115.16 48.91,115 48.67,114.76 48.51,114.76 45.2,118.07 44.79,118.07 44.38,117.66 44.38,117.25 47.69,113.94 47.69,113.78 47.45,113.54 47.29,113.54 43.98,116.85 43.57,116.85 43.15,116.43 43.15,116.02 46.46,112.71 46.46,112.56 46.23,112.32 46.07,112.32 42.76,115.63 42.35,115.63 41.93,115.21 41.93,114.8 45.24,111.49 45.24,111.33 45,111.09 44.85,111.09 41.54,114.4 41.13,114.4 40.71,113.99 40.71,113.58 44.02,110.27 44.02,110.11 43.78,109.87 43.62,109.87 40.31,113.18 39.9,113.18 39.49,112.77 39.49,112.36 42.8,109.05 42.8,108.89 42.56,108.65 42.4,108.65 39.09,111.96 38.68,111.96 38.27,111.54 38.27,111.13 41.58,107.82 41.58,107.67 41.34,107.43 41.18,107.43 37.87,110.74 37.46,110.74 37.04,110.32 37.04,109.91 40.35,106.6 40.35,106.44 40.12,106.21 39.96,106.21 36.65,109.52 36.24,109.52 35.82,109.1 35.82,108.69 39.13,105.38 39.13,105.22 38.89,104.98 38.74,104.98 35.43,108.29 35.01,108.29 33.91,107.19 33.91,104.43 34.2,104.14 36.7,104.14 36.83,104.01 36.83,103.71 36.7,103.58 33.91,103.58 33.6,103.28 33.6,102.72 33.91,102.41 36.41,102.41 36.54,102.29 36.54,101.98 36.41,101.85 33.78,101.85 33.48,101.55 33.48,100.99 33.78,100.69 36.32,100.69 36.45,100.56 36.45,99.97 37.57,98.85 v1(38.23,98.85)
  BOTTOM w0.114: J4.100 35.91,96.9 35.82,97 35.82,99.02 35.93,99.14 37.52,99.14 37.8,98.85 v1(38.23,98.85) ; v1(207.84,144.95) 208.14,144.65 208.14,144 208.04,143.9 J1.16
OVR_AP: length 330.5
  LAYER3 w0.112: v1(208.74,144.95) 208.44,144.65 208.44,143.27 209.04,142.67 210.26,142.67 211.51,141.43 211.51,120.14 210.69,119.33 49.74,119.33 49.63,119.22 49.63,118.27 49.34,117.98 48.75,117.98 48.46,118.27 48.46,119.22 48.35,119.33 46.48,119.33 45.9,118.75 45.9,118.59 49.21,115.28 49.21,114.87 48.8,114.46 48.39,114.46 45.08,117.77 44.92,117.77 44.68,117.53 44.68,117.37 47.99,114.06 47.99,113.65 47.58,113.23 47.17,113.23 43.85,116.54 43.7,116.54 43.46,116.31 43.46,116.15 46.77,112.84 46.77,112.43 46.35,112.01 45.94,112.01 42.63,115.32 42.47,115.32 42.24,115.09 42.24,114.93 45.55,111.62 45.55,111.21 45.13,110.79 44.72,110.79 41.41,114.1 41.25,114.1 41.02,113.86 41.02,113.7 44.33,110.39 44.33,109.98 43.91,109.57 43.5,109.57 40.19,112.88 40.03,112.88 39.79,112.64 39.79,112.48 43.1,109.17 43.1,108.76 42.69,108.35 42.28,108.35 38.97,111.66 38.81,111.66 38.57,111.42 38.57,111.26 41.88,107.95 41.88,107.54 41.46,107.12 41.05,107.12 37.74,110.43 37.59,110.43 37.35,110.2 37.35,110.04 40.66,106.73 40.66,106.32 40.24,105.9 39.83,105.9 36.52,109.21 36.36,109.21 36.13,108.97 36.13,108.82 39.44,105.51 39.44,105.1 39.02,104.68 38.61,104.68 35.3,107.99 35.14,107.99 34.21,107.06 34.21,104.56 34.33,104.45 36.83,104.45 37.13,104.14 37.13,103.58 36.83,103.28 34.04,103.28 33.91,103.15 33.91,102.85 34.04,102.72 36.54,102.72 36.84,102.41 36.84,101.86 36.54,101.55 33.91,101.55 33.78,101.42 33.78,101.12 33.91,100.99 36.45,100.99 36.75,100.69 36.75,100.1 37.41,99.44 37.52,99.44 37.8,99.72 v1(38.23,99.72)
  BOTTOM w0.114: v1(208.74,144.95) 208.44,144.65 208.44,144 208.54,143.9 J1.14 ; v1(38.23,99.72) 37.8,99.72 37.52,99.44 35.8,99.44 35.51,99.15 35.51,97 35.41,96.9 J4.98
OVR_BN: length 330
  LAYER3 w0.112: v1(209.34,140.71) 209.64,140.41 209.64,137.5 209.53,137.39 209.37,137.39 209.25,137.26 209.25,136.95 209.37,136.83 209.53,136.83 209.64,136.71 209.64,136.38 209.53,136.27 209.37,136.27 209.25,136.14 209.25,135.84 209.37,135.71 209.53,135.71 209.64,135.6 209.64,122.43 209.51,122.3 208.61,122.3 208.49,122.43 208.49,131.03 208.2,131.32 207.61,131.32 207.32,131.03 207.32,122.41 207.21,122.3 206.87,122.3 206.76,122.41 206.76,131.03 206.47,131.32 205.88,131.32 205.59,131.03 205.59,122.41 205.48,122.3 205.14,122.3 205.03,122.41 205.03,131.03 204.74,131.32 204.15,131.32 203.86,131.03 203.86,122.41 203.75,122.3 203.42,122.3 203.3,122.41 203.3,131.03 203.01,131.32 202.43,131.32 202.14,131.03 202.14,122.41 202.02,122.3 201.69,122.3 201.58,122.41 201.58,131.03 201.29,131.32 200.7,131.32 200.41,131.03 200.41,122.41 200.3,122.3 199.96,122.3 199.85,122.41 199.85,131.03 199.56,131.32 198.97,131.32 198.68,131.03 198.68,122.41 198.57,122.3 198.23,122.3 198.12,122.41 198.12,124.32 197.82,124.63 197.26,124.63 196.95,124.32 196.95,122.41 196.84,122.3 46.3,122.3 32.33,108.33 32.33,98.58 33.13,97.79 33.95,97.79 34.21,98.04 34.21,98.38 34.16,98.42 34.16,98.55 34.25,98.64 v1(34.6,98.64)
  BOTTOM w0.114: J1.10 209.54,141.26 209.64,141.16 209.64,141.01 v1(209.34,140.71) ; J4.94 34.41,96.9 34.31,97 34.31,97.46 34.31,97.93 34.6,98.21 v1(34.6,98.64)
OVR_BP: length 327.6
  LAYER3 w0.112: v1(210.24,140.71) 209.94,140.41 209.94,122.3 209.64,122 208.49,122 208.18,122.3 208.18,130.9 208.07,131.01 207.73,131.01 207.62,130.9 207.62,122.29 207.33,122 206.74,122 206.45,122.29 206.45,130.9 206.34,131.01 206.01,131.01 205.89,130.9 205.89,122.29 205.6,122 205.02,122 204.73,122.29 204.73,130.9 204.61,131.01 204.28,131.01 204.17,130.9 204.17,122.29 203.88,122 203.29,122 203,122.29 203,130.9 202.89,131.01 202.55,131.01 202.44,130.9 202.44,122.29 202.15,122 201.56,122 201.27,122.29 201.27,130.9 201.16,131.01 200.83,131.01 200.71,130.9 200.71,122.29 200.42,122 199.84,122 199.54,122.29 199.54,130.9 199.43,131.01 199.1,131.01 198.99,130.9 198.99,122.29 198.7,122 198.11,122 197.82,122.29 197.82,124.19 197.69,124.32 197.39,124.32 197.26,124.19 197.26,122.29 196.97,122 46.43,122 32.64,108.2 32.64,98.71 33.26,98.09 33.83,98.09 33.91,98.17 33.91,98.25 33.73,98.43 v1(33.73,98.64)
  BOTTOM w0.114: J1.8 210.04,141.26 209.94,141.16 209.94,141.01 v1(210.24,140.71) ; v1(33.73,98.64) 33.73,98.21 34.01,97.93 34.01,97.59 34.01,97 33.91,96.9 J4.92
PARITY_N: length 279.9
  TOP w0.114: J2.172 228.22,32.46 228.13,32.56 227.8,32.56 v1(227.5,32.26)
  LAYER3 w0.112: v1(227.5,32.26) 227.8,32.56 228.25,32.56 228.46,32.35 228.46,31.99 228.14,31.67 224.84,31.67 223.96,30.79 223.8,30.79 223.64,30.95 223.49,30.95 223.25,30.72 223.25,30.56 223.41,30.4 223.41,30.24 221.79,28.63 220.55,28.63 220.43,28.74 220.43,28.96 220.31,29.08 220,29.08 219.88,28.96 219.88,28.74 219.76,28.63 219.43,28.63 219.32,28.74 219.32,29.01 219.19,29.13 218.89,29.13 218.76,29.01 218.76,28.74 218.65,28.63 218.24,28.63 217.81,28.19 217.81,13.64 217.42,13.26 146.19,13.26 146.08,13.37 146.08,16.09 145.79,16.38 145.2,16.38 144.91,16.09 144.91,13.37 144.8,13.26 144.47,13.26 144.35,13.37 144.35,16.09 144.06,16.38 143.48,16.38 143.19,16.09 143.19,13.37 143.07,13.26 142.74,13.26 142.63,13.37 142.63,16.09 142.34,16.38 141.75,16.38 141.46,16.09 141.46,13.37 141.35,13.26 141.01,13.26 140.9,13.37 140.9,16.09 140.61,16.38 140.02,16.38 139.73,16.09 139.73,13.37 139.62,13.26 139.28,13.26 139.17,13.37 139.17,16.09 138.88,16.38 138.29,16.38 138,16.09 138,13.37 137.89,13.26 137.56,13.26 137.45,13.37 137.45,16.09 137.16,16.38 136.57,16.38 136.28,16.09 136.28,13.37 136.17,13.26 135.83,13.26 135.72,13.37 135.72,16.09 135.43,16.38 134.84,16.38 134.55,16.09 134.55,13.37 134.44,13.26 134.1,13.26 133.99,13.37 133.99,16.09 133.7,16.38 133.11,16.38 132.82,16.09 132.82,13.37 132.71,13.26 132.38,13.26 132.26,13.37 132.26,16.09 131.97,16.38 131.39,16.38 131.1,16.09 131.1,13.37 130.98,13.26 130.65,13.26 130.54,13.37 130.54,16.09 130.25,16.38 129.66,16.38 129.37,16.09 129.37,13.37 129.26,13.26 128.92,13.26 128.81,13.37 128.81,16.09 128.52,16.38 127.93,16.38 127.64,16.09 127.64,13.37 127.53,13.26 127.19,13.26 127.08,13.37 127.08,16.09 126.79,16.38 126.2,16.38 125.91,16.09 125.91,13.46 125.79,13.34 125.08,13.34 124.95,13.46 124.95,16.22 124.66,16.51 124.07,16.51 123.78,16.22 123.78,13.37 123.67,13.26 123.34,13.26 123.22,13.37 123.22,16.22 122.93,16.51 122.35,16.51 122.06,16.22 122.06,13.37 121.94,13.26 121.61,13.26 121.5,13.37 121.5,16.22 121.21,16.51 120.62,16.51 120.33,16.22 120.33,13.37 120.22,13.26 119.88,13.26 119.77,13.37 119.77,16.22 119.48,16.51 118.89,16.51 118.6,16.22 118.6,13.37 118.49,13.26 118.15,13.26 118.04,13.37 118.04,16.22 117.75,16.51 117.16,16.51 116.87,16.22 116.87,13.37 116.76,13.26 116.43,13.26 116.32,13.37 116.32,16.22 116.03,16.51 115.44,16.51 115.15,16.22 115.15,13.46 115.02,13.34 114.19,13.34 114.06,13.46 114.06,16.37 113.77,16.66 113.18,16.66 112.89,16.37 112.89,13.37 112.78,13.26 112.45,13.26 112.33,13.37 112.33,16.37 112.04,16.66 111.46,16.66 111.17,16.37 111.17,12.95 111.04,12.83 110.73,12.83 110.61,12.95 110.61,16.37 110.32,16.66 101.37,16.66 101.14,16.89 101.14,22.61 101.28,22.75 102.4,22.75 v1(102.88,22.26)
  BOTTOM w0.114: v1(102.88,22.26) J3.F10
PARITY_P: length 280
  TOP w0.114: v1(227.5,33.16) 227.8,32.86 228.13,32.86 228.22,32.96 J2.170
  LAYER3 w0.112: v1(102.88,23.53) 102.4,23.05 101.16,23.05 100.84,22.73 100.84,16.76 101.24,16.36 110.19,16.36 110.3,16.25 110.3,12.83 110.61,12.52 111.17,12.52 111.47,12.83 111.47,16.25 111.58,16.36 111.92,16.36 112.03,16.25 112.03,13.24 112.32,12.95 112.91,12.95 113.2,13.24 113.2,16.25 113.31,16.36 113.65,16.36 113.76,16.25 113.76,13.34 114.06,13.03 115.15,13.03 115.45,13.34 115.45,16.09 115.56,16.21 115.9,16.21 116.01,16.09 116.01,13.24 116.3,12.95 116.89,12.95 117.18,13.24 117.18,16.09 117.29,16.21 117.63,16.21 117.74,16.09 117.74,13.24 118.03,12.95 118.62,12.95 118.91,13.24 118.91,16.09 119.02,16.21 119.35,16.21 119.46,16.09 119.46,13.24 119.75,12.95 120.34,12.95 120.63,13.24 120.63,16.09 120.74,16.21 121.08,16.21 121.19,16.09 121.19,13.24 121.48,12.95 122.07,12.95 122.36,13.24 122.36,16.09 122.47,16.21 122.81,16.21 122.92,16.09 122.92,13.24 123.21,12.95 123.8,12.95 124.09,13.24 124.09,16.09 124.2,16.21 124.53,16.21 124.65,16.09 124.65,13.34 124.95,13.03 125.91,13.03 126.22,13.34 126.22,15.97 126.33,16.08 126.67,16.08 126.78,15.97 126.78,13.24 127.07,12.95 127.66,12.95 127.95,13.24 127.95,15.97 128.06,16.08 128.39,16.08 128.5,15.97 128.5,13.24 128.79,12.95 129.38,12.95 129.67,13.24 129.67,15.97 129.78,16.08 130.12,16.08 130.23,15.97 130.23,13.24 130.52,12.95 131.11,12.95 131.4,13.24 131.4,15.97 131.51,16.08 131.85,16.08 131.96,15.97 131.96,13.24 132.25,12.95 132.84,12.95 133.13,13.24 133.13,15.97 133.24,16.08 133.57,16.08 133.69,15.97 133.69,13.24 133.98,12.95 134.56,12.95 134.85,13.24 134.85,15.97 134.97,16.08 135.3,16.08 135.41,15.97 135.41,13.24 135.7,12.95 136.29,12.95 136.58,13.24 136.58,15.97 136.69,16.08 137.03,16.08 137.14,15.97 137.14,13.24 137.43,12.95 138.02,12.95 138.31,13.24 138.31,15.97 138.42,16.08 138.76,16.08 138.87,15.97 138.87,13.24 139.16,12.95 139.75,12.95 140.04,13.24 140.04,15.97 140.15,16.08 140.48,16.08 140.59,15.97 140.59,13.24 140.88,12.95 141.47,12.95 141.76,13.24 141.76,15.97 141.88,16.08 142.21,16.08 142.32,15.97 142.32,13.24 142.61,12.95 143.2,12.95 143.49,13.24 143.49,15.97 143.6,16.08 143.94,16.08 144.05,15.97 144.05,13.24 144.34,12.95 144.93,12.95 145.22,13.24 145.22,15.97 145.33,16.08 145.66,16.08 145.78,15.97 145.78,13.24 146.07,12.95 217.55,12.95 218.11,13.51 218.11,28.07 218.36,28.32 221.92,28.32 224.97,31.37 228.27,31.37 228.76,31.86 228.76,32.48 228.38,32.86 227.8,32.86 v1(227.5,33.16)
  BOTTOM w0.114: v1(102.88,23.53) J3.F11
PRESENT: length 200.5
  TOP w0.165: J2.21 215.48,79.97 214.5,78.99 v1(206.88,78.99)
  LAYER3 w0.124: v1(206.88,78.99) 206.88,79.46 175.63,110.72 62.46,110.72 53.47,101.73 53.47,91.68 52.88,91.1 v1(52.41,91.1)
  BOTTOM w0.165: J4.145 v1(52.41,91.1)
SYNCA_N: length 279.9
  TOP w0.114: J2.177 222.49,30.96 222.4,31.06 220.75,31.06 v1(220.47,30.77)
  LAYER3 w0.112: v1(101.61,17.18) 102.09,17.67 148.36,17.67 148.47,17.55 148.47,15.15 148.76,14.86 149.35,14.86 149.64,15.15 149.64,17.55 149.75,17.67 150.08,17.67 150.2,17.55 150.2,15.15 150.49,14.86 151.07,14.86 151.36,15.15 151.36,17.55 151.48,17.67 151.81,17.67 151.92,17.55 151.92,15.15 152.21,14.86 152.8,14.86 153.09,15.15 153.09,17.55 153.2,17.67 153.54,17.67 153.65,17.55 153.65,15.15 153.94,14.86 154.53,14.86 154.82,15.15 154.82,17.55 154.93,17.67 155.27,17.67 155.38,17.55 155.38,15.15 155.67,14.86 156.26,14.86 156.55,15.15 156.55,17.55 156.66,17.67 156.99,17.67 157.1,17.55 157.1,15.15 157.39,14.86 157.98,14.86 158.27,15.15 158.27,17.55 158.39,17.67 158.72,17.67 158.83,17.55 158.83,15.15 159.12,14.86 159.71,14.86 160,15.15 160,17.55 160.11,17.67 160.45,17.67 160.56,17.55 160.56,15.15 160.85,14.86 161.44,14.86 161.73,15.15 161.73,17.55 161.84,17.67 162.17,17.67 162.29,17.55 162.29,15.15 162.58,14.86 163.16,14.86 163.45,15.15 163.45,17.55 163.57,17.67 163.9,17.67 164.01,17.55 164.01,15.15 164.3,14.86 164.89,14.86 165.18,15.15 165.18,17.55 165.29,17.67 165.63,17.67 165.74,17.55 165.74,15.15 166.03,14.86 166.62,14.86 166.91,15.15 166.91,17.55 167.02,17.67 167.36,17.67 167.47,17.55 167.47,15.15 167.76,14.86 168.35,14.86 168.64,15.15 168.64,17.55 168.75,17.67 169.08,17.67 169.2,17.55 169.2,15.15 169.49,14.86 170.07,14.86 170.36,15.15 170.36,17.55 170.48,17.67 170.81,17.67 170.92,17.55 170.92,15.15 171.21,14.86 171.8,14.86 172.09,15.15 172.09,17.55 172.2,17.67 172.54,17.67 172.65,17.55 172.65,15.15 172.94,14.86 173.53,14.86 173.82,15.15 173.82,17.55 173.93,17.67 174.27,17.67 174.38,17.55 174.38,15.15 174.67,14.86 175.26,14.86 175.55,15.15 175.55,17.55 175.66,17.67 175.99,17.67 176.1,17.55 176.1,15.15 176.39,14.86 176.98,14.86 177.27,15.15 177.27,17.55 177.38,17.67 177.72,17.67 177.83,17.55 177.83,15.15 178.12,14.86 178.71,14.86 179,15.15 179,17.55 179.11,17.67 179.45,17.67 179.56,17.55 179.56,15.15 179.85,14.86 180.44,14.86 180.73,15.15 180.73,17.55 180.84,17.67 181.17,17.67 181.29,17.55 181.29,15.15 181.58,14.86 182.16,14.86 182.45,15.15 182.45,17.55 182.57,17.67 182.9,17.67 183.01,17.55 183.01,15.15 183.3,14.86 183.89,14.86 184.18,15.15 184.18,17.55 184.29,17.67 184.63,17.67 184.74,17.55 184.74,15.15 185.03,14.86 185.62,14.86 185.91,15.15 185.91,17.55 186.02,17.67 186.36,17.67 186.47,17.55 186.47,15.15 186.76,14.86 187.35,14.86 187.64,15.15 187.64,17.55 187.75,17.67 188.08,17.67 188.19,17.55 188.19,15.15 188.48,14.86 189.07,14.86 189.36,15.15 189.36,17.55 189.47,17.67 189.81,17.67 189.92,17.55 189.92,15.15 190.21,14.86 190.8,14.86 191.09,15.15 191.09,17.55 191.2,17.67 191.54,17.67 191.65,17.55 191.65,15.15 191.94,14.86 192.53,14.86 192.82,15.15 192.82,17.55 192.93,17.67 193.26,17.67 193.38,17.55 193.38,15.15 193.67,14.86 194.25,14.86 194.54,15.15 194.54,17.55 194.66,17.67 194.99,17.67 195.1,17.55 195.1,15.53 195.41,15.23 195.97,15.23 196.27,15.53 196.27,17.55 196.38,17.67 215.65,17.67 215.95,17.97 215.95,30.86 216.14,31.06 220.19,31.06 v1(220.47,30.77)
  BOTTOM w0.114: v1(101.61,17.18) J3.E6
SYNCA_P: length 279.9
  TOP w0.114: v1(220.47,31.64) 220.75,31.36 222.4,31.36 222.49,31.46 J2.175
  LAYER3 w0.112: v1(101.61,18.45) 102.09,17.97 148.48,17.97 148.77,17.68 148.77,15.28 148.89,15.16 149.22,15.16 149.33,15.28 149.33,17.68 149.62,17.97 150.21,17.97 150.5,17.68 150.5,15.28 150.61,15.16 150.95,15.16 151.06,15.28 151.06,17.68 151.35,17.97 151.94,17.97 152.23,17.68 152.23,15.28 152.34,15.16 152.68,15.16 152.79,15.28 152.79,17.68 153.08,17.97 153.67,17.97 153.96,17.68 153.96,15.28 154.07,15.16 154.4,15.16 154.51,15.28 154.51,17.68 154.8,17.97 155.39,17.97 155.68,17.68 155.68,15.28 155.79,15.16 156.13,15.16 156.24,15.28 156.24,17.68 156.53,17.97 157.12,17.97 157.41,17.68 157.41,15.28 157.52,15.16 157.86,15.16 157.97,15.28 157.97,17.68 158.26,17.97 158.85,17.97 159.14,17.68 159.14,15.28 159.25,15.16 159.58,15.16 159.7,15.28 159.7,17.68 159.99,17.97 160.57,17.97 160.86,17.68 160.86,15.28 160.98,15.16 161.31,15.16 161.42,15.28 161.42,17.68 161.71,17.97 162.3,17.97 162.59,17.68 162.59,15.28 162.7,15.16 163.04,15.16 163.15,15.28 163.15,17.68 163.44,17.97 164.03,17.97 164.32,17.68 164.32,15.28 164.43,15.16 164.77,15.16 164.88,15.28 164.88,17.68 165.17,17.97 165.76,17.97 166.05,17.68 166.05,15.28 166.16,15.16 166.49,15.16 166.6,15.28 166.6,17.68 166.89,17.97 167.48,17.97 167.77,17.68 167.77,15.28 167.88,15.16 168.22,15.16 168.33,15.28 168.33,17.68 168.62,17.97 169.21,17.97 169.5,17.68 169.5,15.28 169.61,15.16 169.95,15.16 170.06,15.28 170.06,17.68 170.35,17.97 170.94,17.97 171.23,17.68 171.23,15.28 171.34,15.16 171.67,15.16 171.79,15.28 171.79,17.68 172.08,17.97 172.66,17.97 172.95,17.68 172.95,15.28 173.07,15.16 173.4,15.16 173.51,15.28 173.51,17.68 173.8,17.97 174.39,17.97 174.68,17.68 174.68,15.28 174.79,15.16 175.13,15.16 175.24,15.28 175.24,17.68 175.53,17.97 176.12,17.97 176.41,17.68 176.41,15.28 176.52,15.16 176.86,15.16 176.97,15.28 176.97,17.68 177.26,17.97 177.85,17.97 178.14,17.68 178.14,15.28 178.25,15.16 178.58,15.16 178.69,15.28 178.69,17.68 178.98,17.97 179.57,17.97 179.86,17.68 179.86,15.28 179.98,15.16 180.31,15.16 180.42,15.28 180.42,17.68 180.71,17.97 181.3,17.97 181.59,17.68 181.59,15.28 181.7,15.16 182.04,15.16 182.15,15.28 182.15,17.68 182.44,17.97 183.03,17.97 183.32,17.68 183.32,15.28 183.43,15.16 183.76,15.16 183.88,15.28 183.88,17.68 184.17,17.97 184.75,17.97 185.04,17.68 185.04,15.28 185.16,15.16 185.49,15.16 185.6,15.28 185.6,17.68 185.89,17.97 186.48,17.97 186.77,17.68 186.77,15.28 186.88,15.16 187.22,15.16 187.33,15.28 187.33,17.68 187.62,17.97 188.21,17.97 188.5,17.68 188.5,15.28 188.61,15.16 188.95,15.16 189.06,15.28 189.06,17.68 189.35,17.97 189.94,17.97 190.23,17.68 190.23,15.28 190.34,15.16 190.67,15.16 190.79,15.28 190.79,17.68 191.08,17.97 191.66,17.97 191.95,17.68 191.95,15.28 192.07,15.16 192.4,15.16 192.51,15.28 192.51,17.68 192.8,17.97 193.39,17.97 193.68,17.68 193.68,15.28 193.79,15.16 194.13,15.16 194.24,15.28 194.24,17.68 194.53,17.97 195.12,17.97 195.41,17.68 195.41,15.66 195.54,15.53 195.84,15.53 195.97,15.66 195.97,17.68 196.26,17.97 215.52,17.97 215.65,18.1 215.65,30.99 216.02,31.36 220.19,31.36 v1(220.47,31.64)
  BOTTOM w0.114: v1(101.61,18.45) J3.E7
TXEN: length 204.8
  TOP w0.165: J2.27 v1(220.09,78.47)
  LAYER3 w0.124: v1(49.91,91.69) 50.55,91.69 51.18,92.33 51.18,101.85 61.06,111.73 176.3,111.73 v1(211.2,76.83)
  BOTTOM w0.165: 49.91,89.81 v1(49.91,91.69) ; v1(220.09,78.47) 218.46,76.83 v1(211.2,76.83)
TXSP1: length 212
  LAYER3 w0.124: v1(36.91,91.65) 37.72,92.46 37.72,92.46 37.85,92.58 37.85,93.22 38.23,93.6 38.23,95.63 40.89,98.3 40.89,103.12 54.38,116.61 177.9,116.61 v1(215.77,78.74)
  BOTTOM w0.165: J4.103 v1(36.91,91.65) ; v1(215.77,78.74) R1.1
TXSP2: length 212
  LAYER3 w0.124: v1(37.41,91.11) 38.51,92.2 39.37,92.2 41.66,94.49 41.66,102.62 55.14,116.1 177.76,116.1 215.26,78.6 215.26,77.98 v1(215.77,77.47)
  BOTTOM w0.165: J4.105 v1(37.41,91.11) ; v1(215.77,77.47) R2.1
TXSP3: length 211.8
  LAYER3 w0.124: v1(215.77,76.2) 214.76,77.22 214.76,78.39 177.55,115.6 55.91,115.6 42.93,102.62 42.93,93.85 40.89,91.82 39.11,91.82 v1(38.41,91.13)
  BOTTOM w0.165: v1(215.77,76.2) R3.1 ; J4.109 v1(38.41,91.13)
TXSP4: length 211.8
  LAYER3 w0.124: v1(215.77,74.93) 214.25,76.45 214.25,78.18 177.34,115.09 56.79,115.09 43.81,102.11 43.81,93.09 41.91,91.19 v1(39.24,91.19)
  BOTTOM w0.165: J4.111 38.92,90.86 v1(39.24,91.19) ; v1(215.77,74.93) R4.1
TXSP5: length 210.3
  LAYER3 w0.124: v1(215.77,71.12) 213.74,73.15 213.74,77.97 177.13,114.58 57.56,114.58 45.21,102.23 45.21,92.2 v1(46.23,91.19)
  BOTTOM w0.165: v1(46.23,91.19) 46.41,91.01 J4.121 ; v1(215.77,71.12) R7.1
TXSP6: length 208.7
  LAYER3 w0.124: v1(215.77,69.85) 213.23,72.39 213.23,77.76 176.92,114.07 58.45,114.07 46.91,102.53 v1(46.91,91.61)
  BOTTOM w0.165: J4.123 v1(46.91,91.61) ; v1(215.77,69.85) R9.1
